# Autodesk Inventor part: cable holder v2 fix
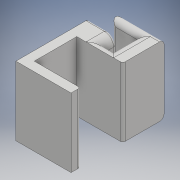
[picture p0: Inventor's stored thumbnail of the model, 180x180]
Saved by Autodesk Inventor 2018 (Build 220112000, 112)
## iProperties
Created: 2018-04
Part Number: cable holder v2 fix
Material: Generic
Document SubType Name: Modeling
Designer: ville.myllys
Density: 1 g/cm^3
Appearance: Default
Part Number: Part5_3DPrint
Author: ville.myllys
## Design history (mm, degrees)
sketch "Sketch1"
  geometry: L1 (0, 0)-(24, 0); L2 (24, 0)-(24, 4); L3 (24, 4)-(4, 4); L4 (4, 4)-(4, 22.5); L5 (4, 22.5)-(24, 22.5); L6 (24, 22.5)-(24, 26.5); L7 (24, 26.5)-(0, 26.5); L8 (0, 26.5)-(0, 0); L9 (0, 26.5)-(12, 26.5); L10 (12, 26.5)-(12, 31.5); L11 (12, 31.5)-(0, 31.5); L12 (0, 31.5)-(0, 26.5); L13 (24, 26.5)-(16, 26.5); L14 (16, 26.5)-(16, 36.5); L15 (16, 36.5)-(5, 36.5); L16 (5, 36.5)-(5, 40.5); L17 (5, 40.5)-(24, 40.5); L18 (24, 40.5)-(24, 26.5)
  constraints: 36 end point, 13 perpendicular, 5 point on line, 1 horizontal, 1 midpoint, 1 vertical
  dimensions: "d0" = 24 distance of L1.start L1.end; "d1" = 4 distance of L1.end L2.end; "d2" = 20 distance of L2.end L3.end; "d3" = 18.5 distance of L3.end L4.end; "d4" = 4 distance of L5.end L6.end; "d5" = 12 distance of L7.end L9.end; "d6" = 5 distance of L9.end L10.end; "d7" = 8 distance of L6.end L13.end; "d8" = 10 distance of L13.end L14.end; "d9" = 11 distance of L14.end L15.end; "d10" = 4 distance of L15.end L16.end; "d14" = 5 distance between parallel lines of L12 L16 (derived)
extrude "Extrusion2" new body sketch "Sketch1" distance "d15" = 30; taper "d16" = 0 deg
fillet "Fillet5" dims "d17" = 4
fillet "Fillet6"
fillet "Fillet7"
fillet "Fillet8"
fillet "Fillet9" dims "d18" = 1
fillet "Fillet10" dims "d19" = 1
body "Solid2"
